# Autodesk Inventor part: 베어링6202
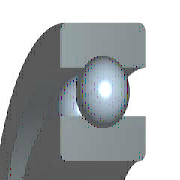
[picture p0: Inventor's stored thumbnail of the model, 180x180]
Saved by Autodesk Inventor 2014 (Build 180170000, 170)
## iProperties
IsCustomPart: 0
Company: 한국ATC센터
Created: 2014-12
Part Number: 베어링6202
Material: 강, 연강
Description: 깊은 그루브 볼 베어링
Document SubType Name: Modeling
Standard: KS B 2023
Designer: KYOUNG IL JANG
Standards Organization: KS
Language: ko-KR
Size Designation: 6202 - 15 x 35 x 11
Categories: <MemberInstance><Categories><Category DisplayName="샤프트 부품" InternalName="7f7aeb1f-a693-4053-b835-cee3144e0d98" Mnemonic="SHFT"><Category DisplayName="베어링" Inter
Density: 7.86 g/cm^3
Mass: 45.8725 g
Surface Area: 51.5584 cm^2
Volume: 5.83619 cm^3
Appearance: 크롬 - 광택 검은색
Author: KYOUNG IL JANG
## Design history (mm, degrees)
sketch "스케치" dims "d0" = 5.2 (= -0.26 x WD + 0.26 x BD)
  geometry: L1 (2.9, 12.5)-(8.1, 12.5); L2 (5.5, 12.5)-(5.5, 9.9); L3 (5.5, 12.5)-(5.5, 15.1); L4 (3.568, 10.76)-(0, 10.76); L5 (0, 7.5)-(11, 7.5); L6 (3.568, 14.24)-(0, 14.24); L7 (0, 17.5)-(11, 17.5); L8 (11, 7.5)-(11, 10.76); L9 (7.432, 10.76)-(11, 10.76); L10 (7.432, 14.24)-(11, 14.24); L11 (11, 17.5)-(11, 14.24); L12 (-1.4, 0)-(8.4, 0) reference; L13 (0, -0.3)-(0, 5.3) reference
  constraints: 22 end point, 4 point on line, 2 collinear, 2 perpendicular, 2 symmetric about line, 1 midpoint, 1 parallel, 14 other
  dimensions: "d9" = 15 diameter of L5 L12 (= WD); "d11" = 35 diameter of L7 L12 (= BD); "d12" = 11 distance between parallel lines of L8 L13 (= KB); "d13" = 21.52 diameter of L9 L12 (= 0.326 x BD + 0.674 x WD)
revolve "본체" stored, may be unused: angle "d6" = 90 deg
revolve "볼" stored, may be unused: angle "d7" = 90 deg
pattern_circular "IDS_ARRAYBALL[SIMPL:T]" dims angle "d3" = 360 deg
body "Solid1"
fillet "모깎기1" dims "d1" = 0.6 (= KRS)
other parameters: "WD" = 15 [user parameter; used in 5 equation terms], "BD" = 35 [user parameter; used in 5 equation terms], "KB" = 11 [user parameter; used in 1 equation term], "KRS" = 0.6 [user parameter; used in 1 equation term], "d4" = 0, "d5" = 0, "d8" = 0, "d14" = 0, "d15" = 0, "BBA" = 0 [user parameter], "BC0" = 3750000 [user parameter], "BC" = 7800000 [user parameter], "BR" = 17.5 (= 0.5 x BD) [user parameter], "WR" = 7.5 (= 0.5 x WD) [user parameter]
